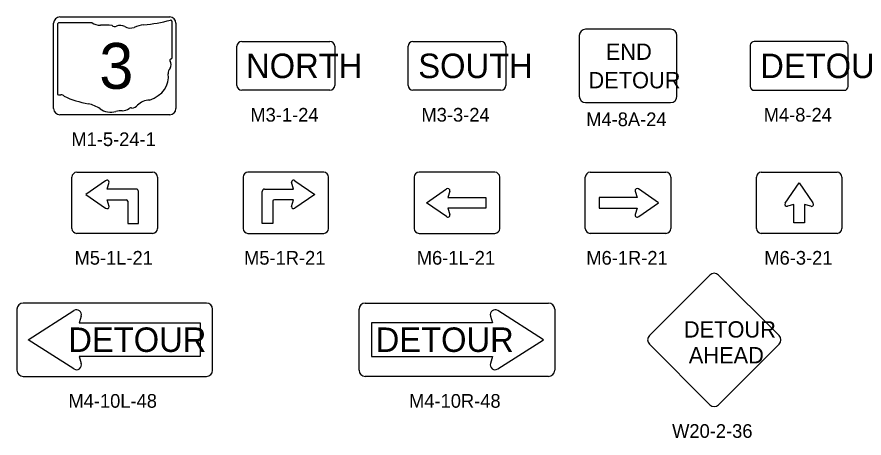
# Model space of a CAD drawing. Extents: x -15.3 to 34, y 0 to 22.
# Drawn here: x -15.29 to -6.63, y 2.92 to 7.23 of the extents above; entities that cross this region are included whole.
import ezdxf

# ---------------------------------------------------------------- set-up
doc = ezdxf.new("R2010")
doc.units = 0
doc.layers.add('SC_Scratch1', color=7, linetype='Continuous')
doc.layers.add('SN_P_Signs', color=7, linetype='Continuous')

msp = doc.modelspace()

# ---------------------------------------------------------------- linework, layer by layer
at = {"layer": 'SN_P_Signs'}
for p, q in [((-14.8764, 7.1539), (-14.8764, 6.4424)), ((-14.5217, 7.1661), (-14.8649, 7.1661)), ((-13.7046, 6.8116), (-13.7046, 7.1838)), ((-12.9905, 6.9775), (-12.0905, 6.9775)), ((-11.2405, 6.9775), (-10.3405, 6.9775)), ((-13.0405, 6.5275), (-13.0405, 6.9275)), ((-12.0405, 6.9275), (-12.0405, 6.5275)), ((-11.2905, 6.5275), (-11.2905, 6.9275)), ((-10.2905, 6.9275), (-10.2905, 6.5275)), ((-13.7047, 6.8117), (-13.7046, 6.8116)), ((-12.0905, 6.4775), (-12.9905, 6.4775)), ((-10.3405, 6.4775), (-11.2405, 6.4775)), ((-14.678, 5.64), (-13.903, 5.64)), ((-12.153, 5.64), (-12.928, 5.64)), ((-10.403, 5.64), (-11.178, 5.64)), ((-10.4029, 5.64), (-10.403, 5.64)), ((-9.428, 5.64), (-8.653, 5.64)), ((-7.678, 5.64), (-6.903, 5.64)), ((-14.728, 5.065), (-14.728, 5.59)), ((-14.3833, 5.5532), (-14.5873, 5.4134)), ((-13.853, 5.59), (-13.853, 5.065)), ((-12.978, 5.59), (-12.978, 5.065)), ((-12.4476, 5.5532), (-12.2436, 5.4134)), ((-12.103, 5.065), (-12.103, 5.59)), ((-11.228, 5.59), (-11.228, 5.065)), ((-10.353, 5.065), (-10.353, 5.59)), ((-9.478, 5.065), (-9.478, 5.59)), ((-8.603, 5.59), (-8.603, 5.065)), ((-7.728, 5.065), (-7.728, 5.59)), ((-6.853, 5.59), (-6.853, 5.065)), ((-14.3685, 5.4681), (-14.3477, 5.5384)), ((-14.0716, 5.4681), (-14.3685, 5.4681)), ((-14.0716, 5.4681), (-14.0716, 5.4681)), ((-12.7593, 5.4681), (-12.4624, 5.4681)), ((-12.7593, 5.4681), (-12.7593, 5.4681)), ((-12.4624, 5.4681), (-12.4832, 5.5384)), ((-11.103, 5.3275), (-10.8961, 5.4697)), ((-8.728, 5.3275), (-8.9349, 5.4697)), ((-7.4326, 5.3237), (-7.2905, 5.5306)), ((-7.2905, 5.5306), (-7.1507, 5.3266)), ((-14.5873, 5.4134), (-14.3833, 5.2737)), ((-14.0482, 5.1165), (-14.0482, 5.4447)), ((-12.7827, 5.1165), (-12.7827, 5.4447)), ((-12.2436, 5.4134), (-12.4476, 5.2737)), ((-10.8643, 5.4463), (-10.8842, 5.3822)), ((-10.8842, 5.3822), (-10.4936, 5.3822)), ((-10.4936, 5.3822), (-10.4936, 5.2727)), ((-8.9467, 5.3822), (-9.3373, 5.3822)), ((-9.3373, 5.3822), (-9.3373, 5.2727)), ((-8.9666, 5.4463), (-8.9467, 5.3822)), ((-14.3477, 5.2884), (-14.3685, 5.3587)), ((-14.3685, 5.3587), (-14.1732, 5.3587)), ((-14.1576, 5.3431), (-14.1576, 5.1165)), ((-12.6733, 5.3431), (-12.6733, 5.1165)), ((-12.4624, 5.3587), (-12.6577, 5.3587)), ((-12.4832, 5.2884), (-12.4624, 5.3587)), ((-10.899, 5.1877), (-11.103, 5.3275)), ((-8.932, 5.1877), (-8.728, 5.3275)), ((-7.3452, 5.3118), (-7.4093, 5.2919)), ((-7.3452, 5.1243), (-7.3452, 5.3118)), ((-7.1716, 5.2919), (-7.2358, 5.3118)), ((-7.2358, 5.3118), (-7.2358, 5.1243)), ((-10.4936, 5.2727), (-10.8842, 5.2727)), ((-10.8842, 5.2727), (-10.8643, 5.2087)), ((-9.3373, 5.2727), (-8.9467, 5.2727)), ((-8.9467, 5.2727), (-8.9666, 5.2087)), ((-14.1576, 5.1165), (-14.0482, 5.1165)), ((-14.1576, 5.1165), (-14.0482, 5.1165)), ((-12.6733, 5.1165), (-12.7827, 5.1165)), ((-7.2358, 5.1243), (-7.3452, 5.1243)), ((-13.903, 5.015), (-14.678, 5.015)), ((-12.928, 5.015), (-12.153, 5.015)), ((-11.178, 5.015), (-10.403, 5.015)), ((-8.653, 5.015), (-9.428, 5.015)), ((-6.903, 5.015), (-7.678, 5.015)), ((-15.1759, 3.9275), (-14.7072, 4.2262)), ((-14.6328, 4.1687), (-14.655, 4.0994)), ((-10.4482, 4.1687), (-10.4259, 4.0994)), ((-9.905, 3.9275), (-10.3737, 4.2262)), ((-14.655, 4.0994), (-13.4155, 4.0994)), ((-13.4155, 4.0994), (-13.4155, 3.7556)), ((-10.4259, 4.0994), (-11.6655, 4.0994)), ((-11.6655, 4.0994), (-11.6655, 3.7556)), ((-14.7072, 3.6288), (-15.1759, 3.9275)), ((-10.3737, 3.6288), (-9.905, 3.9275)), ((-13.4155, 3.7556), (-14.655, 3.7556)), ((-14.655, 3.7556), (-14.6328, 3.6863)), ((-11.6655, 3.7556), (-10.4259, 3.7556)), ((-10.4259, 3.7556), (-10.4482, 3.6863))]:
    msp.add_line(p, q, dxfattribs=at)
for points in [[(-14.853, 7.2275), (-13.728, 7.2275)], [(-14.9155, 6.29), (-14.9155, 7.165)], [(-13.6655, 7.165), (-13.6655, 6.29)], [(-9.5405, 7.0375), (-9.5405, 6.4175)], [(-8.6055, 7.1025), (-9.4755, 7.1025)], [(-8.5405, 6.4175), (-8.5405, 7.0375)], [(-7.7905, 6.9375), (-7.7905, 6.5175)], [(-6.8305, 6.9775), (-7.7505, 6.9775)], [(-6.7905, 6.5175), (-6.7905, 6.9375)], [(-7.7505, 6.4775), (-6.8305, 6.4775)], [(-9.4755, 6.3525), (-8.6055, 6.3525)], [(-13.728, 6.2275), (-14.853, 6.2275)], [(-8.8226, 3.9699), (-8.2039, 4.5887)], [(-8.1155, 4.5887), (-7.4968, 3.9699)], [(-13.353, 4.3025), (-15.228, 4.3025)], [(-11.728, 4.3025), (-9.853, 4.3025)], [(-15.2905, 4.24), (-15.2905, 3.615)], [(-13.2905, 3.615), (-13.2905, 4.24)], [(-11.7905, 3.615), (-11.7905, 4.24)], [(-9.7905, 4.24), (-9.7905, 3.615)], [(-8.2039, 3.2628), (-8.8226, 3.8816)], [(-7.4968, 3.8816), (-8.1155, 3.2628)], [(-15.228, 3.5525), (-13.353, 3.5525)], [(-9.853, 3.5525), (-11.728, 3.5525)]]:
    msp.add_lwpolyline(points, dxfattribs=at)
for centre, radius, start, end in [((-14.853, 7.165), 0.0625, 90, 180), ((-13.728, 7.165), 0.0625, 0, 90), ((-9.4755, 7.0375), 0.065, 90, 180), ((-8.6055, 7.0375), 0.065, 0, 90), ((-12.9905, 6.9275), 0.05, 90, 180), ((-12.0905, 6.9275), 0.05, 0, 90), ((-11.2405, 6.9275), 0.05, 90, 180), ((-10.3405, 6.9275), 0.05, 0, 90), ((-7.7505, 6.9375), 0.04, 90, 180), ((-6.8305, 6.9375), 0.04, 0, 90), ((-12.9905, 6.5275), 0.05, 180, 270), ((-12.0905, 6.5275), 0.05, 270, 0), ((-11.2405, 6.5275), 0.05, 180, 270), ((-10.3405, 6.5275), 0.05, 270, 0), ((-7.7505, 6.5175), 0.04, 180, 270), ((-6.8305, 6.5175), 0.04, 270, 0), ((-9.4755, 6.4175), 0.065, 180, 270), ((-8.6055, 6.4175), 0.065, 270, 0), ((-14.853, 6.29), 0.0625, 180, 270), ((-13.728, 6.29), 0.0625, 270, 0), ((-14.678, 5.59), 0.05, 90, 180), ((-13.903, 5.59), 0.05, 0, 90), ((-12.9279, 5.59), 0.05, 90, 180), ((-12.1529, 5.59), 0.05, 0, 90), ((-11.1779, 5.59), 0.05, 90, 180), ((-10.4029, 5.59), 0.05, 0, 90), ((-9.4279, 5.59), 0.05, 90, 180), ((-8.6529, 5.59), 0.05, 0, 90), ((-7.678, 5.59), 0.05, 90, 180), ((-6.903, 5.59), 0.05, 0, 90), ((-14.3685, 5.5384), 0.0209, 0.00165, 134.99986), ((-12.4624, 5.5384), 0.0209, 45.00014, 179.99835), ((-14.0717, 5.4446), 0.0234, 0, 90), ((-12.7592, 5.4446), 0.0234, 90, 180), ((-10.8842, 5.4525), 0.0209, 342.79539, 124.58878), ((-8.9467, 5.4525), 0.0209, 55.41122, 197.20461), ((-14.3685, 5.2884), 0.0209, 225.00014, 0.00165), ((-14.1732, 5.3431), 0.0156, 0, 90), ((-12.6577, 5.343), 0.0156, 90, 180), ((-12.4624, 5.2884), 0.0209, 179.99835, 314.99986), ((-7.4155, 5.3118), 0.0209, 145.41122, 287.20461), ((-7.1655, 5.3118), 0.0209, 252.79539, 45.00956), ((-10.8842, 5.2025), 0.0209, 224.99044, 17.20461), ((-8.9467, 5.2025), 0.0209, 162.79539, 315.00956), ((-14.678, 5.065), 0.05, 180, 270), ((-13.903, 5.065), 0.05, 270, 360), ((-12.9279, 5.065), 0.05, 180, 270), ((-12.1529, 5.065), 0.05, 270, 0), ((-11.1779, 5.065), 0.05, 180, 270), ((-10.4029, 5.065), 0.05, 270, 0), ((-9.4279, 5.065), 0.05, 180, 270), ((-8.6529, 5.065), 0.05, 270, 360), ((-7.678, 5.065), 0.05, 180, 270), ((-6.903, 5.065), 0.05, 270, 0), ((-8.1597, 4.5445), 0.0625, 45, 135), ((-15.228, 4.24), 0.0625, 90, 180), ((-13.353, 4.24), 0.0625, 0, 90), ((-11.728, 4.24), 0.0625, 90, 180), ((-9.853, 4.24), 0.0625, 0, 90), ((-14.6804, 4.184), 0.05, 342.18111, 122.51085), ((-10.4006, 4.184), 0.05, 57.48915, 197.81889), ((-8.7784, 3.9258), 0.0625, 135, 225), ((-7.541, 3.9258), 0.0625, 315, 45), ((-14.6804, 3.671), 0.05, 237.48915, 17.81889), ((-10.4006, 3.671), 0.05, 162.18111, 302.51085), ((-15.228, 3.615), 0.0625, 180, 270), ((-13.353, 3.615), 0.0625, 270, 0), ((-11.728, 3.615), 0.0625, 180, 270), ((-9.853, 3.615), 0.0625, 270, 360), ((-8.1597, 3.307), 0.0625, 225, 315)]:
    msp.add_arc(centre, radius, start, end, dxfattribs=at)
for centre, major_axis, start_param, end_param in [((-14.122, 8.1362), (1.2427, 0), 4.814394, 5.042369), ((-13.7176, 7.1853), (0.013, 0), 6.141152, 7.989035), ((-14.863, 7.1554), (0.0136, 0), 1.712693, 3.28349), ((-14.44, 7.2487), (0.1317, 0), 4.042523, 4.731795), ((-14.3963, 6.7667), (0.4727, 0), 1.404758, 1.657858), ((-14.289, 7.1591), (0.038, 0), 3.836095, 5.185415), ((-14.2332, 7.0769), (0.079, 0), 0.950623, 2.079405), ((-14.1313, 7.1897), (0.095, 0), 4.081561, 5.145723), ((-13.9635, 6.9488), (0.25, 0), 1.699011, 2.107814), ((-13.7076, 6.7842), (0.0202, 0), 1.883978, 3.671073), ((-13.836, 6.7372), (0.1212, 0), 5.934695, 6.695948), ((-13.7185, 6.8101), (0.014, 0), 5.05454, 6.418171), ((-13.6578, 6.6558), (0.0882, 0), 2.387724, 3.262537), ((-14.0524, 6.6084), (0.3108, 0), 5.101752, 6.440018), ((-14.8629, 6.4408), (0.0137, 0), 3.00124, 4.508301), ((-14.8608, 6.5136), (0.1045, 0), 4.665946, 4.897461), ((-14.8394, 6.4013), (0.0377, 0), 0.519207, 1.627899), ((-14.3636, 7.0406), (0.8974, 0), 4.195997, 4.488961), ((-14.6312, 6.1227), (0.2808, 0), 0.823519, 1.323587), ((-14.137, 6.3734), (0.1004, 0), 4.937069, 5.64225), ((-13.9213, 6.2426), (0.1702, 0), 1.647645, 2.488434), ((-14.3275, 6.3978), (0.1782, 0), 4.026481, 4.996735), ((-14.2245, 6.1518), (0.1464, 0), 1.495662, 1.94098), ((-14.2115, 6.3445), (0.0949, 0), 4.691044, 5.507374), ((-14.1256, 6.2756), (0.0267, 0), 1.147584, 2.315152)]:
    msp.add_ellipse(centre, major_axis=major_axis, ratio=0.8, start_param=start_param, end_param=end_param, dxfattribs=at)

# ---------------------------------------------------------------- texts
at = {"layer": 'SC_Scratch1'}
for s, p in [('M3-1-24', (-12.9033, 6.1575)), ('M3-3-24', (-11.1533, 6.1575)), ('M4-8A-24', (-9.4686, 6.1111)), ('M4-8-24', (-7.6533, 6.1575)), ('M1-5-24-1', (-14.7339, 5.9075)), ('M5-1L-21', (-14.7013, 4.695)), ('M5-1R-21', (-12.9676, 4.695)), ('M6-1L-21', (-11.2013, 4.695)), ('M6-1R-21', (-9.4676, 4.695)), ('M6-3-21', (-7.647, 4.695)), ('M4-10L-48', (-14.764, 3.2325)), ('M4-10R-48', (-11.2803, 3.2325)), ('W20-2-36', (-8.59, 2.9245))]:
    msp.add_text(s, height=0.14, dxfattribs=at).set_placement(p)
at = {"layer": 'SN_P_Signs'}
for s, height, p in [('3', 0.4688, (-14.4485, 6.4925)), ('END', 0.16667, (-9.2686, 6.789)), ('NORTH', 0.25, (-12.9471, 6.6025)), ('SOUTH', 0.25, (-11.1861, 6.6025)), ('DETOUR', 0.25, (-7.6888, 6.6025)), ('DETOUR', 0.16667, (-9.4455, 6.4979)), ('DETOUR', 0.16667, (-8.4695, 3.95)), ('DETOUR', 0.25, (-14.7651, 3.8032)), ('DETOUR', 0.25, (-11.6214, 3.8032)), ('AHEAD', 0.16667, (-8.4195, 3.6862))]:
    msp.add_text(s, height=height, dxfattribs=at).set_placement(p)

doc.saveas('drawing.dxf')
